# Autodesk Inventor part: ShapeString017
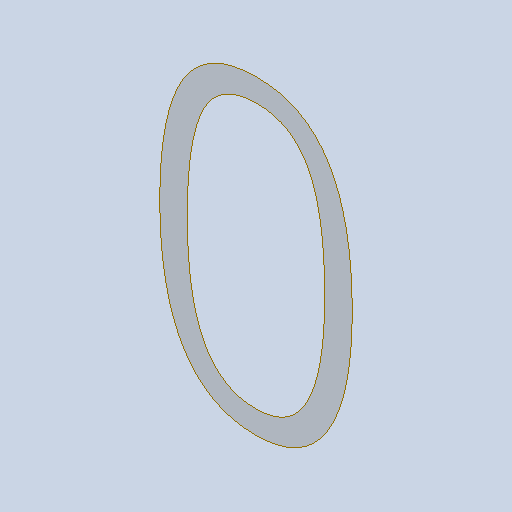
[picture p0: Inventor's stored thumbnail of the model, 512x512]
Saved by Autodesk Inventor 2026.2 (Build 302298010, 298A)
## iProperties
Created: 2026-10
Part Number: ShapeString017
Material: Générique
Document SubType Name: Modeling
Designer: mel
Density: 1 g/cm^3
Appearance: Par défaut
Author: mel
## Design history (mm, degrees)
feature "Composite1"
body "Srf1"
